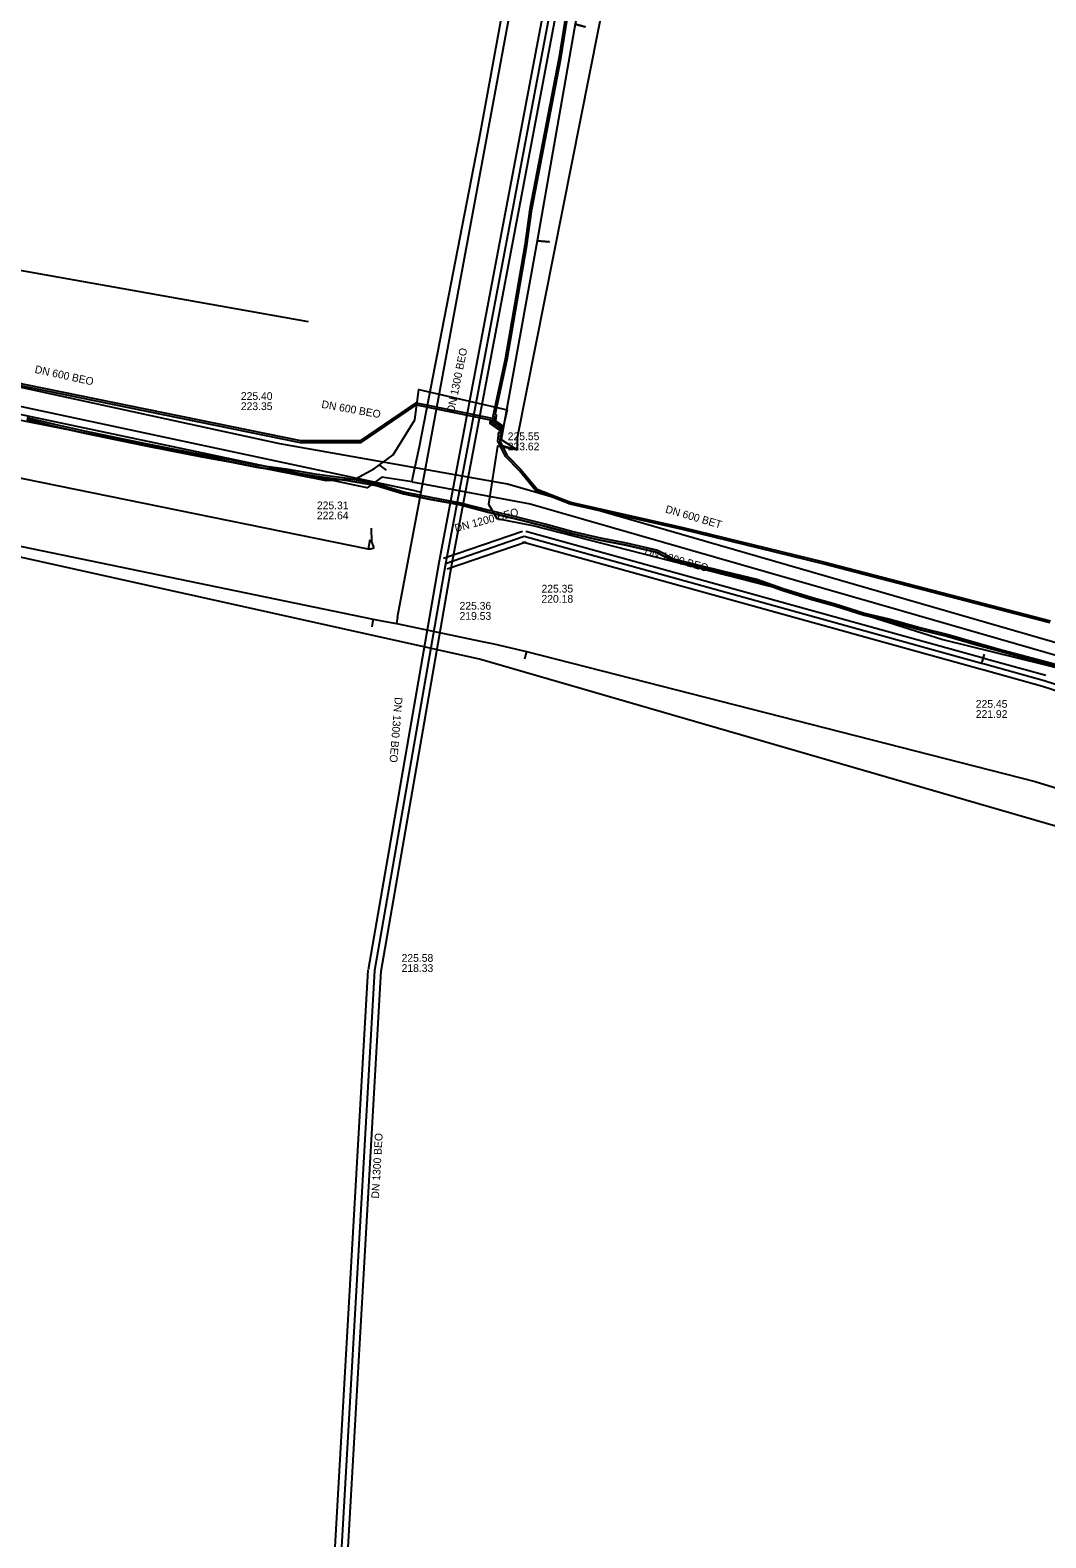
# Model space of a CAD drawing. Extents: x -598233 to -596890, y -1157848 to -1156431.
# Drawn here: x -597486.4 to -597381.4, y -1157746.3 to -1157590.5 of the extents above; entities that cross this region are included whole.
import ezdxf

# ---------------------------------------------------------------- set-up
doc = ezdxf.new("R2010")
doc.units = 0
for name, color, linetype in [('Vrstva 1', 7, 'Continuous'), ('Vrstva 10', 7, 'Continuous'), ('Vrstva 12', 7, 'Continuous'), ('Vrstva 13', 7, 'Continuous'), ('Vrstva 19', 7, 'Continuous'), ('Vrstva 22', 7, 'Continuous'), ('Vrstva 4', 7, 'Continuous'), ('Vrstva 42', 7, 'Continuous'), ('Vrstva 51', 7, 'Continuous'), ('Vrstva 55', 7, 'Continuous'), ('Vrstva 58', 7, 'Continuous'), ('Vrstva 9', 7, 'Continuous')]:
    doc.layers.add(name, color=color, linetype=linetype)

msp = doc.modelspace()

# ---------------------------------------------------------------- linework, layer by layer
at = {"layer": 'Vrstva 1'}
for p, q in [((-597460.57, -1157633.22), (-597497.14, -1157625.28)), ((-597437.03, -1157637.38), (-597460.57, -1157633.22)), ((-597351.72, -1157662.1), (-597437.03, -1157637.38))]:
    msp.add_line(p, q, dxfattribs=at)
msp.add_lwpolyline([(-597449.56, -1157635.95), (-597450.21, -1157635.48)], dxfattribs=at)
at = {"layer": 'Vrstva 10'}
for p, q in [((-597444.1, -1157645.5), (-597432.06, -1157581.82)), ((-597430.78, -1157582.06), (-597442.82, -1157645.74)), ((-597443.66, -1157645.06), (-597435.51, -1157642.26)), ((-597435.12, -1157643.39), (-597443.27, -1157646.19)), ((-597451.43, -1157687.56), (-597444.1, -1157645.51)), ((-597442.82, -1157645.73), (-597450.15, -1157687.78))]:
    msp.add_line(p, q, dxfattribs=at)
for points in [[(-597435.16, -1157642.25), (-597387.87, -1157655.36), (-597387.57, -1157655.44), (-597381.4, -1157657.15)], [(-597381.72, -1157658.31), (-597387.89, -1157656.6), (-597388.19, -1157656.51), (-597435.48, -1157643.4)], [(-597334.82, -1157673.42), (-597346.84, -1157669.55), (-597381.74, -1157658.3)], [(-597456.14, -1157769.61), (-597455.97, -1157766.52), (-597451.44, -1157687.63)], [(-597450.14, -1157687.71), (-597454.67, -1157766.6), (-597454.85, -1157769.69)]]:
    msp.add_lwpolyline(points, dxfattribs=at)
at = {"layer": 'Vrstva 13'}
for p, q in [((-597445.97, -1157638.2), (-597445.66, -1157636.54)), ((-597448.4, -1157651.16), (-597445.97, -1157638.2)), ((-597446.46, -1157638.11), (-597445.97, -1157638.2)), ((-597450.99, -1157651.7), (-597451.07, -1157652.15)), ((-597450.92, -1157651.34), (-597450.99, -1157651.7)), ((-597449.85, -1157651.55), (-597448.51, -1157651.79)), ((-597448.4, -1157651.16), (-597448.51, -1157651.79)), ((-597435.18, -1157655.08), (-597435.28, -1157655.49)), ((-597435.08, -1157654.7), (-597435.18, -1157655.08))]:
    msp.add_line(p, q, dxfattribs=at)
for points in [[(-597445.66, -1157636.54), (-597433.33, -1157569.93), (-597433.08, -1157568.84), (-597428.44, -1157543.5), (-597424.93, -1157524.51)], [(-597446.46, -1157638.11), (-597497.93, -1157627.13), (-597542.05, -1157617.7), (-597622.03, -1157601.6), (-597661.97, -1157593.76), (-597684.46, -1157588.85), (-597760.96, -1157573.18), (-597761.53, -1157573.07), (-597762.19, -1157572.91), (-597821.01, -1157556.59), (-597821.79, -1157556.41)], [(-597603.06, -1157619.91), (-597450.92, -1157651.34), (-597449.85, -1157651.55)], [(-597448.51, -1157651.79), (-597439.68, -1157653.65), (-597438.45, -1157653.91)], [(-597438.45, -1157653.91), (-597435.08, -1157654.7), (-597382.5, -1157668.12), (-597373.56, -1157670.89), (-597320.64, -1157689.18), (-597300.75, -1157696.78)]]:
    msp.add_lwpolyline(points, dxfattribs=at)
at = {"layer": 'Vrstva 19'}
for points in [[(-597446.9, -1157637.15), (-597446.88, -1157636.85), (-597446.13, -1157633.5), (-597439.85, -1157601.05), (-597434.81, -1157573.49), (-597435.99, -1157573.33), (-597436.72, -1157573.23)], [(-597446.9, -1157637.15), (-597450.03, -1157636.66), (-597451.55, -1157637.77), (-597501.01, -1157627.32), (-597507.82, -1157626), (-597559.38, -1157615.3), (-597592.97, -1157608.77), (-597633.32, -1157600.52), (-597678.64, -1157591.26), (-597722.52, -1157582.32), (-597722.64, -1157583.27), (-597724.91, -1157595.04), (-597725.36, -1157597.15)], [(-597446.9, -1157637.15), (-597434.7, -1157639.43), (-597396.36, -1157650.45), (-597360.9, -1157660.7), (-597345.04, -1157665.79), (-597330.89, -1157671.44), (-597330.42, -1157672.33), (-597321.04, -1157676.11), (-597320.16, -1157675.71), (-597313.27, -1157678.34), (-597289.24, -1157687.58), (-597285.67, -1157689.03), (-597267.68, -1157696.53), (-597258.46, -1157692.66), (-597245.73, -1157698.58), (-597223.46, -1157709.57), (-597219.42, -1157711.89), (-597186.03, -1157728.65), (-597143.5, -1157749.83), (-597107.01, -1157767.69), (-597089.09, -1157776.39), (-597078.65, -1157772.6), (-597077.93, -1157772.95)]]:
    msp.add_lwpolyline(points, dxfattribs=at)
at = {"layer": 'Vrstva 22'}
msp.add_lwpolyline([(-597009, -1157734.74), (-597038.36, -1157726.98), (-597042.85, -1157725.8), (-597048.29, -1157737.37), (-597052.31, -1157745.93), (-597068.29, -1157781.63), (-597068.57, -1157782.25), (-597069.3, -1157783.87), (-597069.52, -1157784.38), (-597069.75, -1157784.88), (-597070.02, -1157785.41), (-597070.37, -1157786.1), (-597078.6, -1157807.09), (-597134.97, -1157778.57), (-597188.98, -1157751.64), (-597260.05, -1157717.7), (-597353.38, -1157680.59), (-597353.4, -1157680.57), (-597439.93, -1157655.49), (-597531.04, -1157635.25), (-597620.04, -1157616.48), (-597669.81, -1157606.33)], dxfattribs=at)
at = {"layer": 'Vrstva 42'}
for points in [[(-597437.52, -1157631.35), (-597438.24, -1157630.84), (-597438.18, -1157630.27), (-597438.33, -1157630.24), (-597437.09, -1157624.51), (-597435.04, -1157612.72), (-597434.52, -1157608.99), (-597431.53, -1157593.43), (-597428.96, -1157577.36), (-597428.82, -1157576.6), (-597416.28, -1157579.41), (-597416.12, -1157579.34), (-597416.24, -1157579.21), (-597428.79, -1157576.4), (-597427.36, -1157567.11), (-597423.08, -1157543), (-597423.08, -1157542.98), (-597420.7, -1157542.65), (-597420.32, -1157542.7)], [(-597429.16, -1157577.32), (-597431.73, -1157593.39), (-597434.72, -1157608.95), (-597435.24, -1157612.68), (-597437.29, -1157624.47), (-597438.56, -1157630.4), (-597438.4, -1157630.43), (-597438.45, -1157630.93), (-597437.56, -1157631.56)], [(-597665.88, -1157590.97), (-597646.29, -1157594.86), (-597623.27, -1157599.52), (-597620.49, -1157600.13), (-597593.66, -1157605.98), (-597584.27, -1157607.53), (-597559.52, -1157612.54), (-597557.83, -1157612.79), (-597543.03, -1157615.97), (-597541.18, -1157616.2), (-597532.34, -1157617.98), (-597508.39, -1157622.78), (-597505.4, -1157623.49), (-597486.71, -1157627.32), (-597458.47, -1157633.1), (-597452.16, -1157633.1), (-597446.44, -1157629.21), (-597438.84, -1157630.75), (-597438.88, -1157631.12), (-597437.64, -1157631.99)], [(-597665.84, -1157590.77), (-597646.25, -1157594.66), (-597623.23, -1157599.32), (-597620.45, -1157599.93), (-597593.62, -1157605.78), (-597584.23, -1157607.33), (-597559.48, -1157612.34), (-597557.79, -1157612.59), (-597542.99, -1157615.77), (-597541.14, -1157616), (-597532.3, -1157617.78), (-597508.35, -1157622.58), (-597505.36, -1157623.29), (-597486.67, -1157627.12), (-597458.45, -1157632.9), (-597452.22, -1157632.9), (-597446.48, -1157628.99), (-597438.62, -1157630.59), (-597438.67, -1157631.03), (-597437.6, -1157631.78)], [(-597380.97, -1157651.72), (-597404.43, -1157645.64), (-597418.95, -1157642.08), (-597430.58, -1157639.46), (-597434.1, -1157638.07), (-597435.79, -1157636.02), (-597437.26, -1157634.52), (-597438.04, -1157632.96), (-597437.95, -1157632.02), (-597437.68, -1157632.21)], [(-597437.73, -1157632.42), (-597437.79, -1157632.38), (-597437.84, -1157632.92), (-597437.1, -1157634.4), (-597435.65, -1157635.88), (-597433.98, -1157637.91), (-597430.52, -1157639.26), (-597418.91, -1157641.88), (-597404.39, -1157645.44), (-597380.91, -1157651.52)]]:
    msp.add_lwpolyline(points, dxfattribs=at)
at = {"layer": 'Vrstva 51'}
for points in [[(-597486.73, -1157630.72), (-597483.89, -1157631.42), (-597480.78, -1157632.11), (-597477.79, -1157632.74), (-597474.79, -1157633.36), (-597471.82, -1157633.94), (-597468.64, -1157634.56), (-597465.74, -1157635.09), (-597462.81, -1157635.66), (-597459.97, -1157636.05), (-597456.75, -1157636.59), (-597453.63, -1157637.01), (-597450.62, -1157637.54), (-597447.8, -1157638.41), (-597444.98, -1157638.97), (-597441.9, -1157639.55), (-597438.95, -1157640.31), (-597436.08, -1157641), (-597433.21, -1157641.73), (-597430.43, -1157642.48), (-597427.62, -1157643.15), (-597424.79, -1157643.71), (-597421.66, -1157644.42), (-597420.8, -1157644.86)], [(-597420.8, -1157644.86), (-597419.95, -1157645.29), (-597414.61, -1157646.63), (-597411.34, -1157647.4), (-597408.59, -1157648.38), (-597405.71, -1157649.27), (-597403.22, -1157649.96), (-597400.18, -1157650.93), (-597397.67, -1157651.51), (-597394.33, -1157652.45), (-597391.53, -1157653.14), (-597388.68, -1157653.97), (-597385.88, -1157654.74), (-597382.87, -1157655.55), (-597379.93, -1157656.32)]]:
    msp.add_lwpolyline(points, dxfattribs=at)
at = {"layer": 'Vrstva 55'}
for points in [[(-597395.02, -1157502.25), (-597400.83, -1157508.98), (-597405.26, -1157508.98), (-597410.16, -1157511.36), (-597416.17, -1157515.79), (-597421.39, -1157539.36), (-597419.76, -1157539.49), (-597421.39, -1157539.36), (-597426.13, -1157565.16), (-597425.26, -1157565.3), (-597426.13, -1157565.16), (-597426.61, -1157572.1), (-597430.04, -1157589.85), (-597429.01, -1157590.11), (-597430.04, -1157589.85), (-597433.96, -1157612.23), (-597432.73, -1157612.34), (-597433.96, -1157612.23), (-597437.71, -1157632.78), (-597436.05, -1157633.85)], [(-597388.89, -1157503.69), (-597392.74, -1157511.7), (-597411.8, -1157510.4), (-597436.03, -1157632.61), (-597436.05, -1157633.85)], [(-597495.42, -1157629.2), (-597455.79, -1157637.02), (-597452.77, -1157636.84), (-597450.81, -1157635.77), (-597448.86, -1157634.35), (-597446.63, -1157630.74), (-597446.2, -1157627.6), (-597437.09, -1157629.7), (-597437.89, -1157633.29), (-597436.05, -1157633.85)], [(-597436.05, -1157633.85), (-597438.08, -1157633.47), (-597439.02, -1157639.45), (-597438.16, -1157640.95), (-597434.41, -1157641.67), (-597407.39, -1157648.61), (-597392.05, -1157653.46), (-597376.68, -1157657.24), (-597345.93, -1157667.02), (-597326.34, -1157674.19), (-597316.63, -1157677.91), (-597302.17, -1157684.67), (-597301.11, -1157684.5), (-597287.41, -1157689.48), (-597287.4, -1157689.68), (-597287.23, -1157689.53), (-597265.4, -1157698.9), (-597228.49, -1157716.05), (-597202.3, -1157729.13), (-597200.47, -1157730.02), (-597199.22, -1157730.85), (-597173.32, -1157743.74)]]:
    msp.add_lwpolyline(points, dxfattribs=at)
at = {"layer": 'Vrstva 58'}
for points in [[(-597420.71, -1157644.68), (-597421.59, -1157644.23), (-597424.75, -1157643.51), (-597427.58, -1157642.95), (-597430.38, -1157642.29), (-597433.16, -1157641.54), (-597436.03, -1157640.81), (-597438.9, -1157640.12), (-597441.86, -1157639.35), (-597444.94, -1157638.77), (-597447.75, -1157638.22), (-597450.57, -1157637.35), (-597453.6, -1157636.81), (-597456.72, -1157636.39), (-597459.94, -1157635.85), (-597462.78, -1157635.46), (-597465.7, -1157634.89), (-597468.6, -1157634.36), (-597471.78, -1157633.74), (-597474.75, -1157633.16), (-597477.75, -1157632.54), (-597480.74, -1157631.91), (-597483.84, -1157631.23), (-597486.69, -1157630.53)], [(-597420.8, -1157644.86), (-597421.66, -1157644.42), (-597424.79, -1157643.71), (-597427.62, -1157643.15), (-597430.43, -1157642.48), (-597433.21, -1157641.73), (-597436.08, -1157641), (-597438.95, -1157640.31), (-597441.9, -1157639.55), (-597444.98, -1157638.97), (-597447.8, -1157638.41), (-597450.62, -1157637.54), (-597453.63, -1157637.01), (-597456.75, -1157636.59), (-597459.97, -1157636.05), (-597462.81, -1157635.66), (-597465.74, -1157635.09), (-597468.64, -1157634.56), (-597471.82, -1157633.94), (-597474.79, -1157633.36), (-597477.79, -1157632.74), (-597480.78, -1157632.11), (-597483.89, -1157631.42), (-597486.73, -1157630.72)], [(-597391.53, -1157653.14), (-597394.33, -1157652.45), (-597397.67, -1157651.51), (-597400.18, -1157650.93), (-597403.22, -1157649.96), (-597405.71, -1157649.27), (-597408.59, -1157648.38), (-597411.34, -1157647.4), (-597414.61, -1157646.63), (-597419.95, -1157645.29), (-597420.8, -1157644.86), (-597421.66, -1157644.42), (-597424.79, -1157643.71), (-597427.62, -1157643.15), (-597430.43, -1157642.48), (-597433.21, -1157641.73), (-597436.08, -1157641), (-597438.95, -1157640.31), (-597441.9, -1157639.55), (-597444.98, -1157638.97), (-597447.8, -1157638.41), (-597450.62, -1157637.54), (-597453.63, -1157637.01), (-597456.75, -1157636.59), (-597459.97, -1157636.05), (-597462.81, -1157635.66), (-597465.74, -1157635.09), (-597468.64, -1157634.56), (-597471.82, -1157633.94), (-597474.79, -1157633.36), (-597477.79, -1157632.74), (-597480.78, -1157632.11), (-597483.89, -1157631.42), (-597486.73, -1157630.72)], [(-597420.8, -1157644.86), (-597419.95, -1157645.29), (-597414.61, -1157646.63), (-597411.34, -1157647.4), (-597408.59, -1157648.38), (-597405.71, -1157649.27), (-597403.22, -1157649.96), (-597400.18, -1157650.93), (-597397.67, -1157651.51), (-597394.33, -1157652.45), (-597391.53, -1157653.14), (-597388.68, -1157653.97), (-597385.88, -1157654.74), (-597382.87, -1157655.55), (-597379.93, -1157656.32)], [(-597420.71, -1157644.68), (-597419.88, -1157645.1), (-597414.56, -1157646.44), (-597411.28, -1157647.21), (-597408.53, -1157648.19), (-597405.65, -1157649.08), (-597403.16, -1157649.77), (-597400.13, -1157650.74), (-597397.62, -1157651.32), (-597394.28, -1157652.26), (-597391.48, -1157652.95), (-597388.63, -1157653.78), (-597385.83, -1157654.55), (-597382.82, -1157655.36), (-597379.87, -1157656.13)], [(-597379.93, -1157656.32), (-597382.87, -1157655.55), (-597385.88, -1157654.74), (-597388.68, -1157653.97), (-597391.53, -1157653.14)]]:
    msp.add_lwpolyline(points, dxfattribs=at)
at = {"layer": 'Vrstva 9'}
for p, q in [((-597431.42, -1157581.94), (-597443.46, -1157645.62)), ((-597435.32, -1157642.82), (-597443.46, -1157645.62)), ((-597451.26, -1157643.15), (-597451.46, -1157644.13)), ((-597443.46, -1157645.62), (-597450.79, -1157687.67)), ((-597387.76, -1157654.97), (-597388.03, -1157655.94))]:
    msp.add_line(p, q, dxfattribs=at)
for points in [[(-597457.62, -1157620.6), (-597500.05, -1157613.06)], [(-597450.85, -1157643.99), (-597450.98, -1157644.06), (-597451.21, -1157644.13), (-597451.45, -1157644.13), (-597451.46, -1157644.13), (-597504.9, -1157633.24), (-597512.92, -1157631.6), (-597516.99, -1157630.77), (-597530.67, -1157627.99)], [(-597451.13, -1157641.96), (-597451.1, -1157643.36), (-597450.85, -1157643.99)], [(-597381.56, -1157657.73), (-597387.73, -1157656.02), (-597388.03, -1157655.94), (-597435.32, -1157642.82)], [(-597334.64, -1157672.85), (-597346.66, -1157668.98), (-597381.56, -1157657.73)], [(-597450.79, -1157687.67), (-597455.32, -1157766.56), (-597455.49, -1157769.65)]]:
    msp.add_lwpolyline(points, dxfattribs=at)

# ---------------------------------------------------------------- texts
at = {"layer": 'Vrstva 12'}
for s, rotation, p in [('DN 1300 BEO', 78.4379, (-597442.55, -1157630.05)), ('DN 1200 BEO', 14.8396, (-597442.39, -1157642.35)), ('DN 1200 BEO', 344.5195, (-597422.94, -1157644.66)), ('DN 1300 BEO', 265.3368, (-597448.69, -1157659.39)), ('DN 1300 BEO', 86.7382, (-597450.33, -1157711.26))]:
    msp.add_text(s, height=0.8, rotation=rotation, dxfattribs=at).set_placement(p)
for s, p in [('225.31', (-597456.75, -1157639.99)), ('222.64', (-597456.75, -1157641.03)), ('225.35', (-597433.53, -1157648.6)), ('220.18', (-597433.53, -1157649.65)), ('225.36', (-597442, -1157650.37)), ('219.53', (-597442, -1157651.42)), ('225.45', (-597388.63, -1157660.51)), ('221.92', (-597388.63, -1157661.56)), ('225.58', (-597447.99, -1157686.77)), ('218.33', (-597447.99, -1157687.82))]:
    msp.add_text(s, height=0.8, dxfattribs=at).set_placement(p)
at = {"layer": 'Vrstva 4'}
for s, rotation, p in [('DN 600 BEO', 347.7281, (-597485.97, -1157625.88)), ('DN 600 BEO', 349.9626, (-597456.32, -1157629.5)), ('DN 600 BET', 343.832, (-597420.79, -1157640.32))]:
    msp.add_text(s, height=0.8, rotation=rotation, dxfattribs=at).set_placement(p)
for s, p in [('225.40', (-597464.61, -1157628.69)), ('223.35', (-597464.61, -1157629.74)), ('225.55', (-597437.02, -1157632.85)), ('223.62', (-597437.02, -1157633.9))]:
    msp.add_text(s, height=0.8, dxfattribs=at).set_placement(p)

doc.saveas('drawing.dxf')
